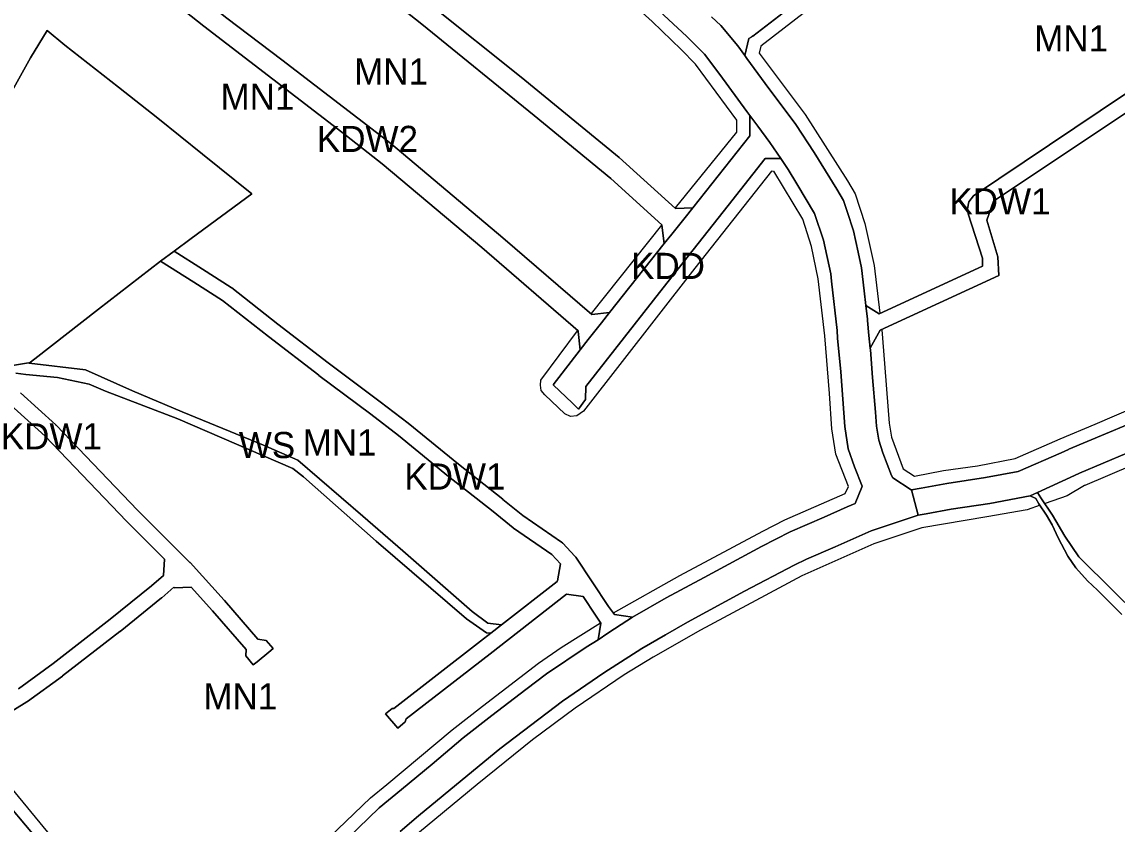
# Model space of a CAD drawing. Extents: x -284239 to -281592, y 34477 to 37267.
# Drawn here: x -283512.6 to -283094, y 34964.3 to 35270.9 of the extents above; entities that cross this region are included whole.
import ezdxf

# ---------------------------------------------------------------- set-up
doc = ezdxf.new("R2010")
doc.units = 0
for name, color, linetype in [('linie_rozgraniczajace', 7, 'Continuous'), ('linie_zabudowy_nieprzekraczalne', 7, 'Continuous'), ('oznaczenia_przeznaczen', 7, 'Continuous')]:
    doc.layers.add(name, color=color, linetype=linetype)

msp = doc.modelspace()

# ---------------------------------------------------------------- linework, layer by layer
at = {"layer": 'linie_rozgraniczajace'}
for points in [[(-283471.305, 35371.537), (-283466.598, 35363.492), (-283457.276, 35356.348), (-283391.394, 35305.482), (-283321.809, 35249.721), (-283284.37, 35219.029), (-283262.84, 35199.528), (-283256.137, 35199.876), (-283259.102, 35196.143), (-283264.139, 35189.807), (-283267.065, 35186.125), (-283267.966, 35193.166), (-283267.989, 35193.296), (-283287.545, 35211.026), (-283316.782, 35235.169), (-283359.777, 35270.028), (-283401.316, 35302.902), (-283436.506, 35330.022), (-283464.859, 35351.891), (-283468.203, 35349.947), (-283468.388, 35352.445), (-283468.764, 35354.903), (-283470.537, 35366.511)], [(-283471.971, 35307.953), (-283467.595, 35328.236), (-283467.33, 35338.158), (-283468.203, 35349.947), (-283464.859, 35351.891), (-283436.506, 35330.022), (-283401.316, 35302.902), (-283359.777, 35270.028), (-283316.782, 35235.169), (-283287.545, 35211.026), (-283267.989, 35193.296), (-283267.966, 35193.166), (-283267.065, 35186.125), (-283287.997, 35159.793), (-283294.778, 35159.039), (-283328.82, 35188.404), (-283371.551, 35224.453), (-283413.223, 35256.402), (-283434.257, 35272.277), (-283468.923, 35299.941)], [(-283475.832, 35295.276), (-283473.019, 35303.101), (-283472.999, 35303.193), (-283471.971, 35307.953), (-283468.923, 35299.941), (-283434.257, 35272.277), (-283413.223, 35256.402), (-283371.551, 35224.453), (-283328.82, 35188.404), (-283294.778, 35159.039), (-283287.997, 35159.793), (-283291.111, 35155.876), (-283296.191, 35149.484), (-283296.144, 35149.444), (-283299.168, 35145.536), (-283299.981, 35152.552), (-283300.009, 35152.798), (-283336.758, 35184.7), (-283374.858, 35216.582), (-283390.336, 35228.687), (-283443.121, 35269.234)], [(-283309.506, 35132.18), (-283299.168, 35145.536), (-283296.144, 35149.444), (-283296.191, 35149.484), (-283291.111, 35155.876), (-283287.997, 35159.793), (-283267.065, 35186.125), (-283264.139, 35189.807), (-283259.102, 35196.143), (-283256.137, 35199.876), (-283234.364, 35227.291), (-283234.364, 35235.105), (-283231.38, 35231.049), (-283226.778, 35224.794), (-283225.367, 35222.739), (-283222.591, 35218.698), (-283228.544, 35218.698), (-283242.698, 35200.707), (-283267.569, 35169.221), (-283297.07, 35131.582), (-283297.128, 35126.569), (-283299.89, 35122.832), (-283302.097, 35125.168)], [(-283459.591, 35179.474), (-283454.38, 35183.239), (-283443.621, 35176.42), (-283432.627, 35169.394), (-283432.492, 35169.286), (-283432.39, 35169.226), (-283414.72, 35155.354), (-283395.494, 35140.584), (-283375.667, 35125.714), (-283364.992, 35117.522), (-283364.929, 35117.47), (-283345.772, 35101.783), (-283328.774, 35088.416), (-283328.75, 35088.395), (-283321.149, 35082.267), (-283306.37, 35072.085), (-283305.95, 35071.736), (-283305.919, 35071.69), (-283305.878, 35071.662), (-283301.251, 35066.704), (-283301.211, 35066.642), (-283300.948, 35066.321), (-283288.402, 35047.502), (-283286.137, 35044.322), (-283279.244, 35043.376), (-283283.595, 35040.532), (-283288.617, 35037.245), (-283292.354, 35034.726), (-283291.273, 35041.078), (-283293.36, 35044.125), (-283293.381, 35044.154), (-283298.1, 35051.232), (-283304.448, 35052.139), (-283333.663, 35029.403), (-283365.738, 35004.525), (-283366.087, 35003.362), (-283368.907, 35000.949), (-283373.576, 35006.464), (-283371.132, 35008.407), (-283370.434, 35008.476), (-283337.344, 35034.141), (-283333.38, 35037.226), (-283329.252, 35040.438), (-283308.001, 35056.977), (-283307.933, 35057.221), (-283306.747, 35063.799), (-283310.042, 35067.329), (-283324.646, 35077.39), (-283324.762, 35077.486), (-283324.828, 35077.525), (-283332.497, 35083.711), (-283349.504, 35097.085), (-283349.544, 35097.118), (-283368.683, 35112.791), (-283379.291, 35120.932), (-283399.108, 35135.795), (-283399.131, 35135.813), (-283418.398, 35150.614), (-283435.98, 35164.417), (-283446.842, 35171.359)], [(-283509.799, 35140.482), (-283507.664, 35142.082), (-283483.295, 35161.074), (-283459.591, 35179.474), (-283446.842, 35171.359), (-283435.98, 35164.417), (-283418.398, 35150.614), (-283399.131, 35135.813), (-283399.108, 35135.795), (-283379.291, 35120.932), (-283368.683, 35112.791), (-283349.544, 35097.118), (-283349.504, 35097.085), (-283332.497, 35083.711), (-283324.828, 35077.525), (-283324.762, 35077.486), (-283324.646, 35077.39), (-283310.042, 35067.329), (-283306.747, 35063.799), (-283307.933, 35057.221), (-283308.001, 35056.977), (-283329.252, 35040.438), (-283334.509, 35041.03), (-283340.462, 35045.528), (-283367.053, 35068.745), (-283382.266, 35081.975), (-283407.137, 35103.406), (-283420.234, 35109.161), (-283451.323, 35121.861), (-283470.373, 35129.93), (-283488.232, 35137.868)]]:
    msp.add_lwpolyline(points, close=True, dxfattribs=at)
for points in [[(-283460.618, 35234.062), (-283475.613, 35245.965), (-283496.173, 35262.042), (-283502.975, 35267.607), (-283509.313, 35257.095), (-283522.917, 35232.825), (-283522.917, 35232.636), (-283523.014, 35232.725), (-283527.552, 35226.283), (-283534.386, 35231.101), (-283550.521, 35241.633), (-283553.587, 35243.683), (-283559.988, 35247.963), (-283568.279, 35253.341), (-283582.285, 35262.753), (-283579.201, 35266.417), (-283588.366, 35276.203), (-283598.698, 35279.683), (-283601.902, 35277.142), (-283617.703, 35288.854), (-283630.702, 35298.362), (-283632.444, 35304.207)], [(-283272.425, 35278.258), (-283258.408, 35265.282), (-283251.738, 35258.612), (-283245.85, 35250.744), (-283235.48, 35236.622), (-283234.364, 35235.105), (-283234.364, 35227.291), (-283256.137, 35199.876), (-283262.84, 35199.528), (-283284.37, 35219.029), (-283321.809, 35249.721), (-283391.394, 35305.482)], [(-283475.832, 35295.276), (-283443.121, 35269.234), (-283390.336, 35228.687), (-283374.858, 35216.582), (-283336.758, 35184.7), (-283300.009, 35152.798), (-283299.981, 35152.552), (-283299.168, 35145.536), (-283309.506, 35132.18), (-283302.097, 35125.168), (-283299.89, 35122.832), (-283297.128, 35126.569), (-283297.07, 35131.582), (-283267.569, 35169.221), (-283242.698, 35200.707), (-283228.544, 35218.698), (-283222.591, 35218.698), (-283219.691, 35214.476), (-283216.408, 35209.005), (-283209.634, 35197.645), (-283206.247, 35187.484), (-283203.433, 35174.56), (-283203.173, 35171.799), (-283200.984, 35152.935), (-283200.828, 35149.965), (-283199.629, 35137.198), (-283198.014, 35116.303), (-283196.763, 35107.757), (-283194.366, 35100.774), (-283191.394, 35093.383), (-283191.53, 35093.112), (-283194.08, 35086.806), (-283197.18, 35085.558), (-283205.934, 35081.598), (-283219.014, 35075.918), (-283229.957, 35070.395), (-283251.894, 35058.462), (-283266.381, 35050.75), (-283279.244, 35043.376), (-283286.137, 35044.322), (-283288.402, 35047.502), (-283300.948, 35066.321), (-283301.211, 35066.642), (-283301.251, 35066.704), (-283305.878, 35071.662), (-283305.919, 35071.69), (-283305.95, 35071.736), (-283306.37, 35072.085), (-283321.149, 35082.267), (-283328.75, 35088.395), (-283328.774, 35088.416), (-283345.772, 35101.783), (-283364.929, 35117.47), (-283364.992, 35117.522), (-283375.667, 35125.714), (-283395.494, 35140.584), (-283414.72, 35155.354), (-283432.39, 35169.226), (-283432.492, 35169.286), (-283432.627, 35169.394), (-283443.621, 35176.42), (-283454.38, 35183.239), (-283447.942, 35188.149), (-283424.754, 35205.154), (-283443.614, 35220.304), (-283460.618, 35234.062)], [(-283388.003, 34958.933), (-283376.07, 34970.45), (-283367.472, 34977.484), (-283355.748, 34987.229), (-283343.919, 34997.286), (-283333.028, 35005.779), (-283320.053, 35015.732), (-283312.08, 35021.725), (-283296.969, 35031.938), (-283292.354, 35034.726), (-283288.617, 35037.245), (-283283.595, 35040.532), (-283279.244, 35043.376), (-283266.381, 35050.75), (-283251.894, 35058.462), (-283229.957, 35070.395), (-283219.014, 35075.918), (-283205.934, 35081.598), (-283197.18, 35085.558), (-283194.08, 35086.806), (-283191.53, 35093.112), (-283191.394, 35093.383), (-283194.366, 35100.774), (-283196.763, 35107.757), (-283198.014, 35116.303), (-283199.629, 35137.198), (-283200.828, 35149.965), (-283200.984, 35152.935), (-283203.173, 35171.799), (-283203.433, 35174.56), (-283206.247, 35187.484), (-283209.634, 35197.645), (-283216.408, 35209.005), (-283219.691, 35214.476), (-283222.591, 35218.698), (-283225.367, 35222.739), (-283226.778, 35224.794), (-283231.38, 35231.049), (-283234.364, 35235.105), (-283235.48, 35236.622), (-283245.85, 35250.744), (-283251.738, 35258.612), (-283258.408, 35265.282), (-283272.425, 35278.258)], [(-283215.037, 35279.622), (-283233.281, 35265.477), (-283233.437, 35265.386), (-283233.637, 35265.224), (-283234.73, 35264.519), (-283236.245, 35257.992), (-283239.002, 35261.765), (-283245.518, 35269.496), (-283249.079, 35272.865)], [(-283081.17, 35249.919), (-283148.903, 35204.411), (-283150.623, 35202.096), (-283151.152, 35199.45), (-283150.888, 35197.466), (-283145.464, 35180.532), (-283145.464, 35177.49), (-283184.972, 35159.367), (-283190.045, 35162.503), (-283190.667, 35168.151), (-283191.656, 35176.853), (-283193.011, 35182.898), (-283194.783, 35191.027), (-283197.232, 35198.479), (-283198.587, 35202.647), (-283201.088, 35206.92), (-283209.791, 35220.938), (-283216.773, 35231.672), (-283228.498, 35247.357), (-283235.48, 35256.945), (-283236.245, 35257.992), (-283234.73, 35264.519), (-283233.637, 35265.224), (-283233.437, 35265.386), (-283233.281, 35265.477), (-283215.037, 35279.622)], [(-283249.079, 35272.865), (-283245.518, 35269.496), (-283239.002, 35261.765), (-283236.245, 35257.992), (-283235.48, 35256.945), (-283228.498, 35247.357), (-283216.773, 35231.672), (-283209.791, 35220.938), (-283201.088, 35206.92), (-283198.587, 35202.647), (-283197.232, 35198.479), (-283194.783, 35191.027), (-283193.011, 35182.898), (-283191.656, 35176.853), (-283190.667, 35168.151), (-283190.045, 35162.503), (-283189.472, 35157.303), (-283189.416, 35156.792), (-283188.86, 35151.045), (-283188.389, 35146.185), (-283188.322, 35145.484), (-283187.488, 35134.958), (-283186.393, 35121.774), (-283185.977, 35116.355), (-283185.143, 35111.04), (-283183.528, 35106.193), (-283180.193, 35097.544), (-283179.79, 35096.569), (-283172.744, 35092.031), (-283172.717, 35091.985)], [(-283522.917, 35232.825), (-283509.313, 35257.095), (-283502.975, 35267.607), (-283496.173, 35262.042), (-283475.613, 35245.965), (-283460.618, 35234.062), (-283443.614, 35220.304), (-283424.754, 35205.154), (-283447.942, 35188.149), (-283454.38, 35183.239), (-283459.591, 35179.474), (-283483.295, 35161.074), (-283507.664, 35142.082), (-283509.799, 35140.482), (-283510.06, 35140.514), (-283524.877, 35138.133)], [(-283077.863, 35244.694), (-283141.198, 35202.325), (-283143.851, 35195.154), (-283139.643, 35181.128), (-283139.246, 35173.984), (-283184.552, 35153.037), (-283188.389, 35146.185), (-283188.86, 35151.045), (-283189.416, 35156.792), (-283189.472, 35157.303), (-283190.045, 35162.503), (-283184.972, 35159.367), (-283145.464, 35177.49), (-283145.464, 35180.532), (-283150.888, 35197.466), (-283151.152, 35199.45), (-283150.623, 35202.096), (-283148.903, 35204.411), (-283081.17, 35249.919)], [(-283075.89, 35122.924), (-283112.522, 35107.515), (-283112.595, 35107.465), (-283115.444, 35106.221), (-283131.821, 35099.031), (-283144.286, 35096.69), (-283159.034, 35094.443), (-283168.858, 35092.657), (-283168.901, 35092.644), (-283168.948, 35092.64), (-283172.556, 35092.013), (-283172.717, 35091.985), (-283172.744, 35092.031), (-283179.79, 35096.569), (-283180.193, 35097.544), (-283183.528, 35106.193), (-283185.143, 35111.04), (-283185.977, 35116.355), (-283186.393, 35121.774), (-283187.488, 35134.958), (-283188.322, 35145.484), (-283188.389, 35146.185), (-283184.552, 35153.037), (-283139.246, 35173.984), (-283139.643, 35181.128), (-283143.851, 35195.154), (-283141.198, 35202.325), (-283077.863, 35244.694)], [(-283524.877, 35138.133), (-283510.06, 35140.514), (-283509.799, 35140.482), (-283488.232, 35137.868), (-283470.373, 35129.93), (-283451.323, 35121.861), (-283420.234, 35109.161), (-283407.137, 35103.406), (-283382.266, 35081.975), (-283367.053, 35068.745), (-283340.462, 35045.528), (-283334.509, 35041.03), (-283329.252, 35040.438), (-283333.38, 35037.226), (-283335.038, 35037.326), (-283342.711, 35042.75), (-283377.239, 35072.383), (-283405.021, 35096.99), (-283408.989, 35100.231), (-283453.042, 35119.149), (-283480.692, 35129.798), (-283486.909, 35132.444), (-283498.948, 35134.958), (-283511.119, 35136.148), (-283514.969, 35136.607)], [(-283514.969, 35136.607), (-283511.119, 35136.148), (-283498.948, 35134.958), (-283486.909, 35132.444), (-283480.692, 35129.798), (-283453.042, 35119.149), (-283408.989, 35100.231), (-283405.021, 35096.99), (-283377.239, 35072.383), (-283342.711, 35042.75), (-283335.038, 35037.326), (-283333.38, 35037.226), (-283337.344, 35034.141), (-283370.434, 35008.476), (-283371.132, 35008.407), (-283373.576, 35006.464), (-283368.907, 35000.949), (-283366.087, 35003.362), (-283365.738, 35004.525), (-283333.663, 35029.403), (-283304.448, 35052.139), (-283298.1, 35051.232), (-283293.381, 35044.154), (-283293.36, 35044.125), (-283291.273, 35041.078), (-283292.354, 35034.726), (-283296.969, 35031.938), (-283312.08, 35021.725), (-283320.053, 35015.732), (-283333.028, 35005.779), (-283343.919, 34997.286), (-283355.748, 34987.229), (-283367.472, 34977.484), (-283376.07, 34970.45), (-283388.003, 34958.933)], [(-283522.352, 35129.294), (-283503.756, 35112.492), (-283472.68, 35080.097), (-283472.655, 35080.08), (-283472.637, 35080.053), (-283458.053, 35065.469), (-283458.424, 35059.341), (-283463.02, 35055.391), (-283478.824, 35042.55), (-283500.658, 35025.661), (-283513.918, 35016.002)], [(-283513.918, 35016.002), (-283500.658, 35025.661), (-283478.824, 35042.55), (-283463.02, 35055.391), (-283458.424, 35059.341), (-283458.053, 35065.469), (-283472.637, 35080.053), (-283472.655, 35080.08), (-283472.68, 35080.097), (-283503.756, 35112.492), (-283522.352, 35129.294)], [(-283520.138, 35005.08), (-283510.66, 35010.962), (-283510.571, 35011.033), (-283510.476, 35011.086), (-283497.09, 35020.836), (-283497.047, 35020.873), (-283497.021, 35020.888), (-283475.125, 35037.827), (-283475.077, 35037.866), (-283459.204, 35050.761), (-283459.148, 35050.81), (-283454.501, 35054.801), (-283454.275, 35054.575), (-283447.842, 35054.767), (-283439.711, 35045.812), (-283426.874, 35030.942), (-283426.945, 35028.56), (-283424.156, 35025.207), (-283422.739, 35026.285), (-283418.24, 35030), (-283416.572, 35031.38), (-283419.299, 35034.451), (-283422.431, 35034.977), (-283435.194, 35049.762), (-283435.22, 35049.781), (-283435.244, 35049.818), (-283448.299, 35064.195), (-283448.355, 35064.234), (-283448.398, 35064.3), (-283468.372, 35084.273), (-283499.501, 35116.723), (-283499.594, 35116.787), (-283499.654, 35116.872), (-283513.192, 35129.104)], [(-283513.192, 35129.104), (-283499.654, 35116.872), (-283499.594, 35116.787), (-283499.501, 35116.723), (-283468.372, 35084.273), (-283448.398, 35064.3), (-283448.355, 35064.234), (-283448.299, 35064.195), (-283435.244, 35049.818), (-283435.22, 35049.781), (-283435.194, 35049.762), (-283422.431, 35034.977), (-283419.299, 35034.451), (-283416.572, 35031.38), (-283418.24, 35030), (-283422.739, 35026.285), (-283424.156, 35025.207), (-283426.945, 35028.56), (-283426.874, 35030.942), (-283439.711, 35045.812), (-283447.842, 35054.767), (-283454.275, 35054.575), (-283454.501, 35054.801), (-283459.148, 35050.81), (-283459.204, 35050.761), (-283475.077, 35037.866), (-283475.125, 35037.827), (-283497.021, 35020.888), (-283497.047, 35020.873), (-283497.09, 35020.836), (-283510.476, 35011.086), (-283510.571, 35011.033), (-283510.66, 35010.962), (-283520.138, 35005.08)], [(-283072.146, 35113.651), (-283108.433, 35098.389), (-283110.362, 35097.498), (-283124.432, 35091.003), (-283127.201, 35089.724), (-283142.698, 35086.817), (-283157.399, 35084.584), (-283167.017, 35082.828), (-283170.044, 35082.295), (-283172.556, 35092.013), (-283168.948, 35092.64), (-283168.901, 35092.644), (-283168.858, 35092.657), (-283159.034, 35094.443), (-283144.286, 35096.69), (-283131.821, 35099.031), (-283115.444, 35106.221), (-283112.595, 35107.465), (-283112.522, 35107.515), (-283075.89, 35122.924)], [(-283087.568, 35045.691), (-283094.449, 35052.454), (-283099.491, 35057.318), (-283104.534, 35062.36), (-283108.627, 35066.394), (-283114.054, 35074.313), (-283118.681, 35082.381), (-283123.219, 35088.995), (-283124.432, 35091.003), (-283110.362, 35097.498), (-283108.433, 35098.389), (-283072.146, 35113.651)], [(-283172.717, 35091.985), (-283172.556, 35092.013), (-283170.044, 35082.295), (-283188.061, 35076.335), (-283201.714, 35070.291), (-283212.761, 35065.497), (-283217.451, 35063.204), (-283236.366, 35053.251), (-283258.252, 35041.474), (-283266.641, 35036.628), (-283275.656, 35031.365), (-283290.195, 35022.142), (-283305.932, 35011.303), (-283329.954, 34993.013), (-283342.199, 34982.956), (-283360.959, 34967.427), (-283368.045, 34961.487)], [(-283368.045, 34961.487), (-283360.959, 34967.427), (-283342.199, 34982.956), (-283329.954, 34993.013), (-283305.932, 35011.303), (-283290.195, 35022.142), (-283275.656, 35031.365), (-283266.641, 35036.628), (-283258.252, 35041.474), (-283236.366, 35053.251), (-283217.451, 35063.204), (-283212.761, 35065.497), (-283201.714, 35070.291), (-283188.061, 35076.335), (-283170.044, 35082.295), (-283167.017, 35082.828), (-283157.399, 35084.584), (-283142.698, 35086.817), (-283127.201, 35089.724), (-283125.058, 35088.758), (-283123.872, 35086.682), (-283120.965, 35082.351), (-283118.889, 35078.614), (-283116.576, 35073.69), (-283112.898, 35066.632), (-283109.843, 35062.212), (-283105.334, 35057.229), (-283101.538, 35053.67), (-283092.254, 35044.386)], [(-283092.254, 35044.386), (-283101.538, 35053.67), (-283105.334, 35057.229), (-283109.843, 35062.212), (-283112.898, 35066.632), (-283116.576, 35073.69), (-283118.889, 35078.614), (-283120.965, 35082.351), (-283123.872, 35086.682), (-283125.058, 35088.758), (-283127.201, 35089.724), (-283124.432, 35091.003), (-283123.219, 35088.995), (-283118.681, 35082.381), (-283114.054, 35074.313), (-283108.627, 35066.394), (-283104.534, 35062.36), (-283099.491, 35057.318), (-283094.449, 35052.454), (-283087.568, 35045.691)], [(-283520.466, 34974.943), (-283507.888, 34959.86)], [(-283507.888, 34959.86), (-283520.466, 34974.943)]]:
    msp.add_lwpolyline(points, dxfattribs=at)
at = {"layer": 'linie_zabudowy_nieprzekraczalne'}
for points in [[(-283262.786, 35199.853), (-283239.361, 35228.789), (-283239.361, 35233.353), (-283255.104, 35254.784), (-283260.66, 35260.341), (-283271.772, 35270.99), (-283307.624, 35303.534), (-283316.487, 35311.008), (-283353.132, 35341.436), (-283365.832, 35352.746), (-283397.185, 35379.073), (-283414.912, 35393.162), (-283435.153, 35410.492), (-283467.961, 35439.861), (-283470.343, 35433.511), (-283469.152, 35390.516), (-283464.531, 35362.043)], [(-283081.14, 35382.909), (-283084.315, 35383.174), (-283111.302, 35359.89), (-283122.812, 35350.63), (-283135.776, 35339.848), (-283146.227, 35329.529), (-283154.165, 35322.65), (-283169.379, 35307.767), (-283212.373, 35275.422), (-283230.233, 35261.663), (-283230.762, 35258.885), (-283213.299, 35235.47), (-283197.028, 35210.202), (-283194.117, 35205.109), (-283190.413, 35193.864), (-283186.841, 35177.724), (-283184.734, 35159.504)], [(-283225.338, 35213.708), (-283226.132, 35213.84), (-283255.368, 35176.732), (-283297.966, 35122.095), (-283300.48, 35120.376), (-283302.861, 35120.111), (-283305.11, 35121.037), (-283312.783, 35128.313), (-283314.106, 35130.033), (-283314.37, 35132.017), (-283314.238, 35133.936), (-283300.225, 35152.757)], [(-283286.466, 35045.072), (-283261.189, 35059.323), (-283229.439, 35076.256), (-283220.972, 35080.556), (-283197.954, 35090.61), (-283196.631, 35093.256), (-283201.525, 35105.691), (-283202.981, 35115.349), (-283203.907, 35128.909), (-283205.759, 35150.869), (-283208.272, 35172.697), (-283210.786, 35185), (-283214.093, 35195.451), (-283225.206, 35213.84)], [(-283294.933, 35159.372), (-283268.078, 35193.239)], [(-283272.589, 35187.58), (-283272.434, 35187.778)], [(-283183.94, 35153.154), (-283183.269, 35145.18), (-283181.152, 35117.531), (-283180.226, 35112.107), (-283175.729, 35100.069), (-283171.495, 35097.291), (-283160.383, 35099.407), (-283147.418, 35101.26), (-283132.998, 35103.972), (-283115.8, 35111.512), (-283102.439, 35117.135), (-283053.623, 35138.169)], [(-283040.526, 34907.716), (-283020.153, 34920.284), (-282999.648, 34936.887), (-282984.038, 34950.116), (-282982.847, 34961.493), (-282981.789, 34966.322), (-282979.01, 34970.687), (-282973.851, 34977.963), (-282971.867, 34982.197), (-282970.676, 34986.033), (-282971.999, 34990.531), (-282975.571, 34997.41), (-282979.804, 35007.663), (-282989.065, 35030.153), (-282991.314, 35042.72), (-282994.489, 35067.525), (-283002.955, 35105.691), (-283005.469, 35128.578), (-283007.321, 35134.266), (-283010.099, 35138.764), (-283011.951, 35139.293), (-283035.367, 35124.609), (-283059.444, 35113.695), (-283106.408, 35093.719)], [(-283106.248, 35093.703), (-283106.521, 35093.703), (-283113.055, 35089.779), (-283121.456, 35086.841)], [(-283123.435, 35086.149), (-283128.368, 35084.425), (-283143.846, 35081.746), (-283168.585, 35077.513), (-283186.973, 35071.428), (-283214.49, 35059.191), (-283253.252, 35038.421), (-283271.376, 35028.102), (-283282.356, 35021.289), (-283301.141, 35008.589), (-283317.413, 34996.418), (-283338.58, 34979.419), (-283364.377, 34958.12), (-283391.364, 34932.389), (-283410.547, 34913.207), (-283427.612, 34895.479)], [(-283533.455, 34995.065), (-283528.287, 34990.2), (-283516.909, 34978.36), (-283488.731, 34943.964), (-283480, 34933.712), (-283467.829, 34916.646), (-283457.378, 34897.596), (-283456.055, 34897.332), (-283430.655, 34923.988), (-283413.06, 34942.112), (-283404.461, 34950.248), (-283379.326, 34974.325), (-283373.108, 34979.419), (-283348.105, 35000.321), (-283336.596, 35009.317), (-283315.164, 35025.721), (-283306.433, 35031.806), (-283291.494, 35041.235)]]:
    msp.add_lwpolyline(points, dxfattribs=at)

# ---------------------------------------------------------------- texts
at = {"layer": 'oznaczenia_przeznaczen'}
for s, p in [('MN1', (-283125.697, 35259.603)), ('MN1', (-283385.612, 35246.912)), ('MN1', (-283436.679, 35237.312)), ('KDW2', (-283399.837, 35221.16)), ('KDW1', (-283158.083, 35197.325)), ('KDD', (-283279.777, 35172.627)), ('KDW1', (-283520.641, 35107.492)), ('WS', (-283429.688, 35104.161)), ('MN1', (-283405.293, 35105.141)), ('KDW1', (-283366.429, 35092.118)), ('MN1', (-283443.223, 35008.085))]:
    msp.add_text(s, height=10, dxfattribs=at).set_placement(p)

doc.saveas('drawing.dxf')
